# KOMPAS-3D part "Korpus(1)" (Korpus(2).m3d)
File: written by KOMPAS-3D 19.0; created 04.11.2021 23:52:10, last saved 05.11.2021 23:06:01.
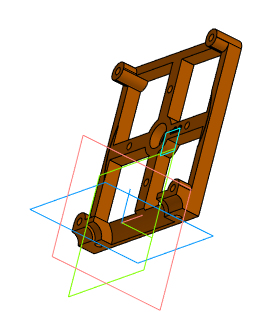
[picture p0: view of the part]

Document properties: Полное имя файла: D:\3D_print\3D проекты Компас 3D\Редуктор (Снова)\Korpus(2).m3d

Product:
- Part/product: Korpus(1)
    Материал: АБС 0603Т ТУ 2214-019-002 03521-96 (density 0 kg/m3)

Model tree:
1. Смещенная плоскость:1  (labels: Подшипник 23 ГОСТ 8338-75\Наружное кольцо; Korpus(1); Операция вращения:1; Операция вращения:1)
     Расстояние = 1.6
2. Эскиз:2  (labels: Подшипник 23 ГОСТ 8338-75\Наружное кольцо; Korpus(1); Скругление:2; Скругление:2)
3. Элемент выдавливания:1  (labels: Korpus(1))
     Расстояние 1 = 11.5
4. Эскиз:3  (labels: Korpus(1))
5. Элемент выдавливания:2
     Расстояние 1 = 34.6; Расстояние 2 = 34.6
6. Эскиз:4  (labels: Korpus(1))
7. Элемент выдавливания:3  (labels: Подшипник 23 ГОСТ 8338-75\Наружное кольцо; Korpus(1); Операция вращения:1; Операция вращения:1)
     Расстояние 1 = 25.2; Смещение 1 = 0.3; Расстояние 2 = 25.2; Смещение 2 = 0.3
8. Эскиз:6  (with: Эскиз:1)  (labels: Korpus(1))
9. Элемент выдавливания:5  (labels: Подшипник 23 ГОСТ 8338-75\Наружное кольцо; Korpus(1); Операция вращения:1; Операция вращения:1)
     Расстояние 2 = 5.9
10. Эскиз:9  (with: Элемент выдавливания:5)
11. Элемент выдавливания:8  (with: Элемент выдавливания:1)
     Расстояние 2 = 4.2; Смещение 2 = 1.4
12. Эскиз:10  (with: Элемент выдавливания:1)  (labels: Гайка М3-6H ГОСТ 5915-70; Korpus(1); Фаска:3; Фаска:3)
13. Элемент выдавливания:9
     Расстояние 2 = 11.5
14. Эскиз:12  (with: Элемент выдавливания:1, Элемент выдавливания:2)  (labels: Гайка М3-6H ГОСТ 5915-70; Korpus(1); Фаска:3; Фаска:3)
15. Элемент выдавливания:10
     Расстояние 2 = 11.5
16. Эскиз:13  (with: Элемент выдавливания:1)  (labels: Korpus(1))
17. Элемент выдавливания:11  (labels: Подшипник 23 ГОСТ 8338-75\Наружное кольцо; Korpus(1); Операция вращения:1; Операция вращения:1)
     Расстояние 1 = 20.9; Расстояние 2 = 20.9
18. Скругление:2  (with: Элемент выдавливания:1)
     Радиус = 4
19. Эскиз:14  (with: Элемент выдавливания:1, Элемент выдавливания:12)  (labels: Korpus(1); Korpus(2))
20. Элемент выдавливания:12  (with: Элемент выдавливания:10)
     Расстояние 2 = 7.41561
21. Эскиз:15  (with: Элемент выдавливания:1, Элемент выдавливания:10)
22. Элемент выдавливания:13  (with: Элемент выдавливания:5)
     Расстояние 2 = 5.6
23. Эскиз:16  (with: Элемент выдавливания:5)
24. Элемент выдавливания:14
25. Эскиз:17  (with: Элемент выдавливания:1)
26. Элемент выдавливания:15
     Расстояние 1 = 69.2
27. Скругление:3  (with: Элемент выдавливания:15)
     Радиус = 3
28. Скругление:4  (with: Элемент выдавливания:15)
     Радиус = 3
29. Эскиз:18  (with: Элемент выдавливания:1)
30. Элемент выдавливания:16  (with: Элемент выдавливания:10)
     Расстояние 2 = 3.60261
31. Скругление:5  (with: Элемент выдавливания:16)  (labels: АБС 0603Т ТУ 2214-019-002 03521-96)
     Радиус = 3

Referenced files in D:\3D_print\3D проекты Компас 3D\Редуктор (Снова)\: R-10 - Reductor.a3d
